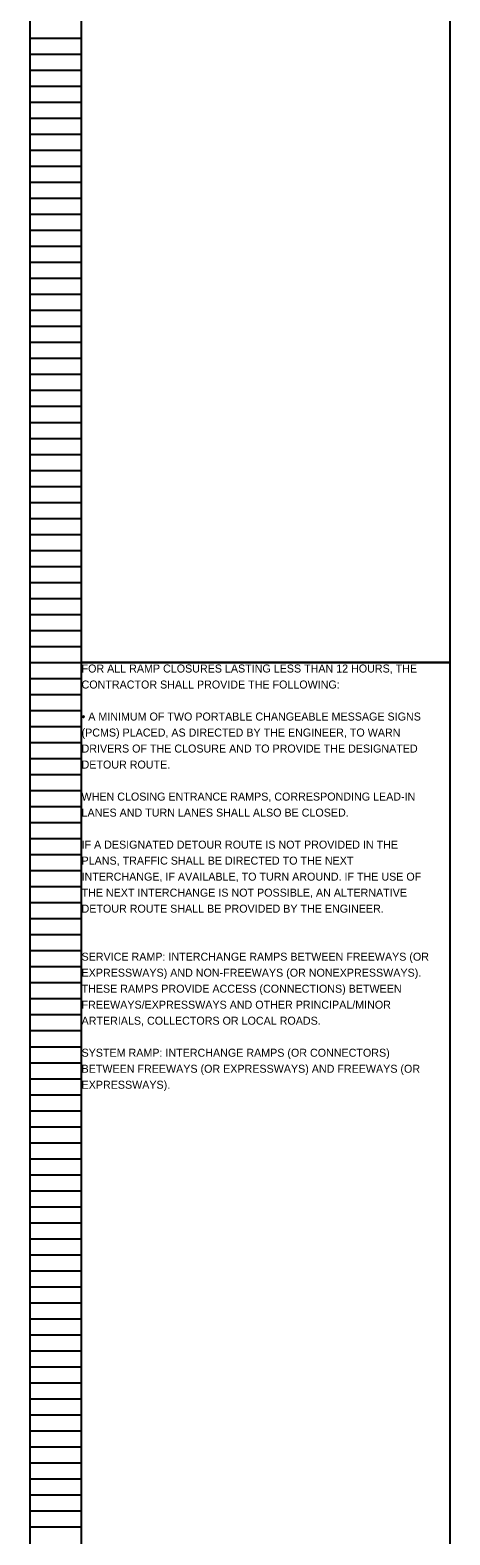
# Model space of a CAD drawing. Extents: x 16463 to 16500, y 5400 to 5823.
# Drawn here: x 16463.05 to 16470.39, y 5505.81 to 5532.13 of the extents above; entities that cross this region are included whole.
import ezdxf

# ---------------------------------------------------------------- set-up
doc = ezdxf.new("R2010")
doc.units = 0
for name, color, linetype in [('Default', 7, 'Continuous'), ('SC_Scratch1', 7, 'Continuous'), ('SH_Data', 7, 'Continuous')]:
    doc.layers.add(name, color=color, linetype=linetype)

msp = doc.modelspace()

# ---------------------------------------------------------------- linework, layer by layer
at = {"layer": 'SC_Scratch1'}
for points in [[(16463.949, 5541.232), (16470.389, 5541.232), (16470.389, 5521.072), (16463.949, 5521.072)], [(16463.949, 5521.072), (16470.389, 5521.072), (16470.389, 5500.912), (16463.949, 5500.912)]]:
    msp.add_lwpolyline(points, close=True, dxfattribs=at)
at = {"layer": 'SH_Data'}
for p, q in [((16463.049, 5521.072), (16463.049, 5541.232)), ((16463.949, 5521.072), (16463.949, 5541.232)), ((16463.049, 5531.992), (16463.949, 5531.992)), ((16463.049, 5531.712), (16463.949, 5531.712)), ((16463.049, 5531.432), (16463.949, 5531.432)), ((16463.049, 5531.152), (16463.949, 5531.152)), ((16463.049, 5530.872), (16463.949, 5530.872)), ((16463.049, 5530.592), (16463.949, 5530.592)), ((16463.049, 5530.312), (16463.949, 5530.312)), ((16463.049, 5530.032), (16463.949, 5530.032)), ((16463.049, 5529.752), (16463.949, 5529.752)), ((16463.049, 5529.472), (16463.949, 5529.472)), ((16463.049, 5529.192), (16463.949, 5529.192)), ((16463.049, 5528.912), (16463.949, 5528.912)), ((16463.049, 5528.632), (16463.949, 5528.632)), ((16463.049, 5528.352), (16463.949, 5528.352)), ((16463.049, 5528.072), (16463.949, 5528.072)), ((16463.049, 5527.792), (16463.949, 5527.792)), ((16463.049, 5527.512), (16463.949, 5527.512)), ((16463.049, 5527.232), (16463.949, 5527.232)), ((16463.049, 5526.952), (16463.949, 5526.952)), ((16463.049, 5526.672), (16463.949, 5526.672)), ((16463.049, 5526.392), (16463.949, 5526.392)), ((16463.049, 5526.112), (16463.949, 5526.112)), ((16463.049, 5525.832), (16463.949, 5525.832)), ((16463.049, 5525.552), (16463.949, 5525.552)), ((16463.049, 5525.272), (16463.949, 5525.272)), ((16463.049, 5524.992), (16463.949, 5524.992)), ((16463.049, 5524.712), (16463.949, 5524.712)), ((16463.049, 5524.432), (16463.949, 5524.432)), ((16463.049, 5524.152), (16463.949, 5524.152)), ((16463.049, 5523.872), (16463.949, 5523.872)), ((16463.049, 5523.592), (16463.949, 5523.592)), ((16463.049, 5523.312), (16463.949, 5523.312)), ((16463.049, 5523.032), (16463.949, 5523.032)), ((16463.049, 5522.752), (16463.949, 5522.752)), ((16463.049, 5522.472), (16463.949, 5522.472)), ((16463.049, 5522.192), (16463.949, 5522.192)), ((16463.049, 5521.912), (16463.949, 5521.912)), ((16463.049, 5521.632), (16463.949, 5521.632)), ((16463.049, 5521.352), (16463.949, 5521.352)), ((16463.049, 5500.912), (16463.049, 5521.072)), ((16463.049, 5521.072), (16463.949, 5521.072)), ((16463.049, 5521.072), (16463.949, 5521.072)), ((16463.949, 5500.912), (16463.949, 5521.072)), ((16463.049, 5520.792), (16463.949, 5520.792)), ((16463.049, 5520.512), (16463.949, 5520.512)), ((16463.049, 5520.232), (16463.949, 5520.232)), ((16463.049, 5519.952), (16463.949, 5519.952)), ((16463.049, 5519.672), (16463.949, 5519.672)), ((16463.049, 5519.392), (16463.949, 5519.392)), ((16463.049, 5519.112), (16463.949, 5519.112)), ((16463.049, 5518.832), (16463.949, 5518.832)), ((16463.049, 5518.552), (16463.949, 5518.552)), ((16463.049, 5518.272), (16463.949, 5518.272)), ((16463.049, 5517.992), (16463.949, 5517.992)), ((16463.049, 5517.712), (16463.949, 5517.712)), ((16463.049, 5517.432), (16463.949, 5517.432)), ((16463.049, 5517.152), (16463.949, 5517.152)), ((16463.049, 5516.872), (16463.949, 5516.872)), ((16463.049, 5516.592), (16463.949, 5516.592)), ((16463.049, 5516.312), (16463.949, 5516.312)), ((16463.049, 5516.032), (16463.949, 5516.032)), ((16463.049, 5515.752), (16463.949, 5515.752)), ((16463.049, 5515.472), (16463.949, 5515.472)), ((16463.049, 5515.192), (16463.949, 5515.192)), ((16463.049, 5514.912), (16463.949, 5514.912)), ((16463.049, 5514.632), (16463.949, 5514.632)), ((16463.049, 5514.352), (16463.949, 5514.352)), ((16463.049, 5514.072), (16463.949, 5514.072)), ((16463.049, 5513.792), (16463.949, 5513.792)), ((16463.049, 5513.512), (16463.949, 5513.512)), ((16463.049, 5513.232), (16463.949, 5513.232)), ((16463.049, 5512.952), (16463.949, 5512.952)), ((16463.049, 5512.672), (16463.949, 5512.672)), ((16463.049, 5512.392), (16463.949, 5512.392)), ((16463.049, 5512.112), (16463.949, 5512.112)), ((16463.049, 5511.832), (16463.949, 5511.832)), ((16463.049, 5511.552), (16463.949, 5511.552)), ((16463.049, 5511.272), (16463.949, 5511.272)), ((16463.049, 5510.992), (16463.949, 5510.992)), ((16463.049, 5510.712), (16463.949, 5510.712)), ((16463.049, 5510.432), (16463.949, 5510.432)), ((16463.049, 5510.152), (16463.949, 5510.152)), ((16463.049, 5509.872), (16463.949, 5509.872)), ((16463.049, 5509.592), (16463.949, 5509.592)), ((16463.049, 5509.312), (16463.949, 5509.312)), ((16463.049, 5509.032), (16463.949, 5509.032)), ((16463.049, 5508.752), (16463.949, 5508.752)), ((16463.049, 5508.472), (16463.949, 5508.472)), ((16463.049, 5508.192), (16463.949, 5508.192)), ((16463.049, 5507.912), (16463.949, 5507.912)), ((16463.049, 5507.632), (16463.949, 5507.632)), ((16463.049, 5507.352), (16463.949, 5507.352)), ((16463.049, 5507.072), (16463.949, 5507.072)), ((16463.049, 5506.792), (16463.949, 5506.792)), ((16463.049, 5506.512), (16463.949, 5506.512)), ((16463.049, 5506.232), (16463.949, 5506.232)), ((16463.049, 5505.952), (16463.949, 5505.952))]:
    msp.add_line(p, q, dxfattribs=at)

# ---------------------------------------------------------------- texts
at = {"layer": 'Default'}
for s, p in [('FOR ALL RAMP CLOSURES LASTING LESS THAN 12 HOURS, THE ', (16463.949, 5520.896)), ('CONTRACTOR SHALL PROVIDE THE FOLLOWING:', (16463.949, 5520.616)), ('• A MINIMUM OF TWO PORTABLE CHANGEABLE MESSAGE SIGNS ', (16463.949, 5520.056)), ('(PCMS) PLACED, AS DIRECTED BY THE ENGINEER, TO WARN ', (16463.949, 5519.776)), ('DRIVERS OF THE CLOSURE AND TO PROVIDE THE DESIGNATED ', (16463.949, 5519.496)), ('DETOUR ROUTE.  ', (16463.949, 5519.216)), ('WHEN CLOSING ENTRANCE RAMPS, CORRESPONDING LEAD-IN ', (16463.949, 5518.656)), ('LANES AND TURN LANES SHALL ALSO BE CLOSED.', (16463.949, 5518.376)), ('IF A DESIGNATED DETOUR ROUTE IS NOT PROVIDED IN THE ', (16463.949, 5517.816)), ('PLANS, TRAFFIC SHALL BE DIRECTED TO THE NEXT ', (16463.949, 5517.536)), ('INTERCHANGE, IF AVAILABLE, TO TURN AROUND. IF THE USE OF ', (16463.949, 5517.256)), ('THE NEXT INTERCHANGE IS NOT POSSIBLE, AN ALTERNATIVE ', (16463.949, 5516.976)), ('DETOUR ROUTE SHALL BE PROVIDED BY THE ENGINEER. ', (16463.949, 5516.696)), ('SERVICE RAMP: INTERCHANGE RAMPS BETWEEN FREEWAYS (OR ', (16463.949, 5515.856)), ('EXPRESSWAYS) AND NON-FREEWAYS (OR NONEXPRESSWAYS). ', (16463.949, 5515.576)), ('THESE RAMPS PROVIDE ACCESS (CONNECTIONS) BETWEEN ', (16463.949, 5515.296)), ('FREEWAYS/EXPRESSWAYS AND OTHER PRINCIPAL/MINOR ', (16463.949, 5515.016)), ('ARTERIALS, COLLECTORS OR LOCAL ROADS.', (16463.949, 5514.736)), ('SYSTEM RAMP: INTERCHANGE RAMPS (OR CONNECTORS) ', (16463.949, 5514.176)), ('BETWEEN FREEWAYS (OR EXPRESSWAYS) AND FREEWAYS (OR ', (16463.949, 5513.896)), ('EXPRESSWAYS).', (16463.949, 5513.616))]:
    msp.add_text(s, height=0.14, dxfattribs=at).set_placement(p)

doc.saveas('drawing.dxf')
